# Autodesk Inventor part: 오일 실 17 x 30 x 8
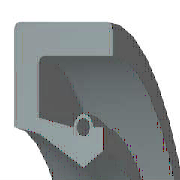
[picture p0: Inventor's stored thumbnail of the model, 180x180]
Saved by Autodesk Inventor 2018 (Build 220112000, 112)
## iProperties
IsCustomPart: 0
Created: 2016-05
Part Number: 오일 실 17 x 30 x 8
Material: 고무
Description: 오일-실
Document SubType Name: Modeling
Standard: KS B 2804
Designer: mduedu
Standards Organization: KS
Language: ko-KR
Size Designation: S - 17 30 8
Categories: <MemberInstance><Categories><Category DisplayName="샤프트 부품" InternalName="7f7aeb1f-a693-4053-b835-cee3144e0d98" Mnemonic="SHFT"><Category DisplayName="실링" Intern
Density: 0.93 g/cm^3
Appearance: 고무 - 검은색 - 버전 1.1
Author: mduedu
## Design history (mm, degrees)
revolve "본체" stored, may be unused: angle "d17" = 90 deg
revolve "스프링1" stored, may be unused: angle "d18" = 90 deg
body "Solid1"
sketch "스케치1"
  geometry: L1 (0, 15)-(8, 15); L2 (8, 15)-(8, 13.75); L3 (8, 13.75)-(1.75, 13.75); L4 (0, 15)-(0, 10.6); L5 (0, 10.6)-(1.75, 10.25); L6 (1.75, 10.25)-(4.9, 8.5); L7 (4.9, 8.5)-(0, 8.5); L8 (6.3, 9.375)-(6.3, 10.6); L9 (0, 0)-(9.586, 0) reference; L10 (4.9, 8.5)-(6.3, 9.375); L11 (0, 18)-(0, -3) reference; L12 (-1.917, 0)-(11.503, 0) reference; L13 (4.2, 10.6)-(1.75, 11.09); L14 (1.75, 11.09)-(1.75, 13.75); L15 (6.3, 10.6)-(5.6, 10.6); C1 r 0.455 at (4.9, 10.6); A1 r 0.7 centre (4.9, 10.6) between (5.6, 10.6) and (4.2, 10.6)
  constraints: 26 end point, 5 horizontal alignment, 4 perpendicular, 2 centre point, 2 collinear, 2 horizontal, 2 parallel, 2 point on circle, 2 point on line, 2 vertical alignment, 1 coincident
  dimensions: "d0" = 30 diameter of L1 L9 (= SD2); "d1" = 18.75 diameter of L8.start L9 (= ABDM); "d2" = 1.25 distance of L1.end L2.end (computed from SD); "d3" = 0.91 diameter of C1 (= SPDI); "d4" = 1.4 diameter of A1 (= SPDA); "d5" = 17 diameter of L6.end L9 (= NND); "d6" = 20.5 diameter of L5.end L9 (= TKDM); "d7" = 21.2 diameter of L4.end L9 (= HLDM); "d8" = 4.9 distance from line of C1.centre L4 (= SPDST); "d9" = 6.3 distance between parallel lines of L8 L4 (= SDI); "d10" = 8 distance between parallel lines of L2 L4 (= SWDT); "d12" = 1.75 distance between parallel lines of L14 L4 (= SD)
fillet "모깎기1" dims "d11" = 0.3 (= RR)
other parameters: "SD2" = 30 [user parameter; used in 1 equation term], "SWDT" = 8 [user parameter; used in 1 equation term], "RR" = 0.3 [user parameter; used in 1 equation term], "SD" = 1.75 [user parameter; used in 2 equation terms], "NND" = 17 [user parameter; used in 1 equation term], "SPDA" = 1.4 [user parameter; used in 1 equation term], "SPDI" = 0.91 [user parameter; used in 1 equation term], "TKDM" = 20.5 [user parameter; used in 1 equation term], "HLDM" = 21.2 [user parameter; used in 1 equation term], "ABDM" = 18.75 [user parameter; used in 1 equation term], "SDI" = 6.3 [user parameter; used in 1 equation term], "SPDST" = 4.9 [user parameter; used in 1 equation term], "d13" = 0, "d14" = 0, "d15" = 0, "LAB" = 0.35 [user parameter]
